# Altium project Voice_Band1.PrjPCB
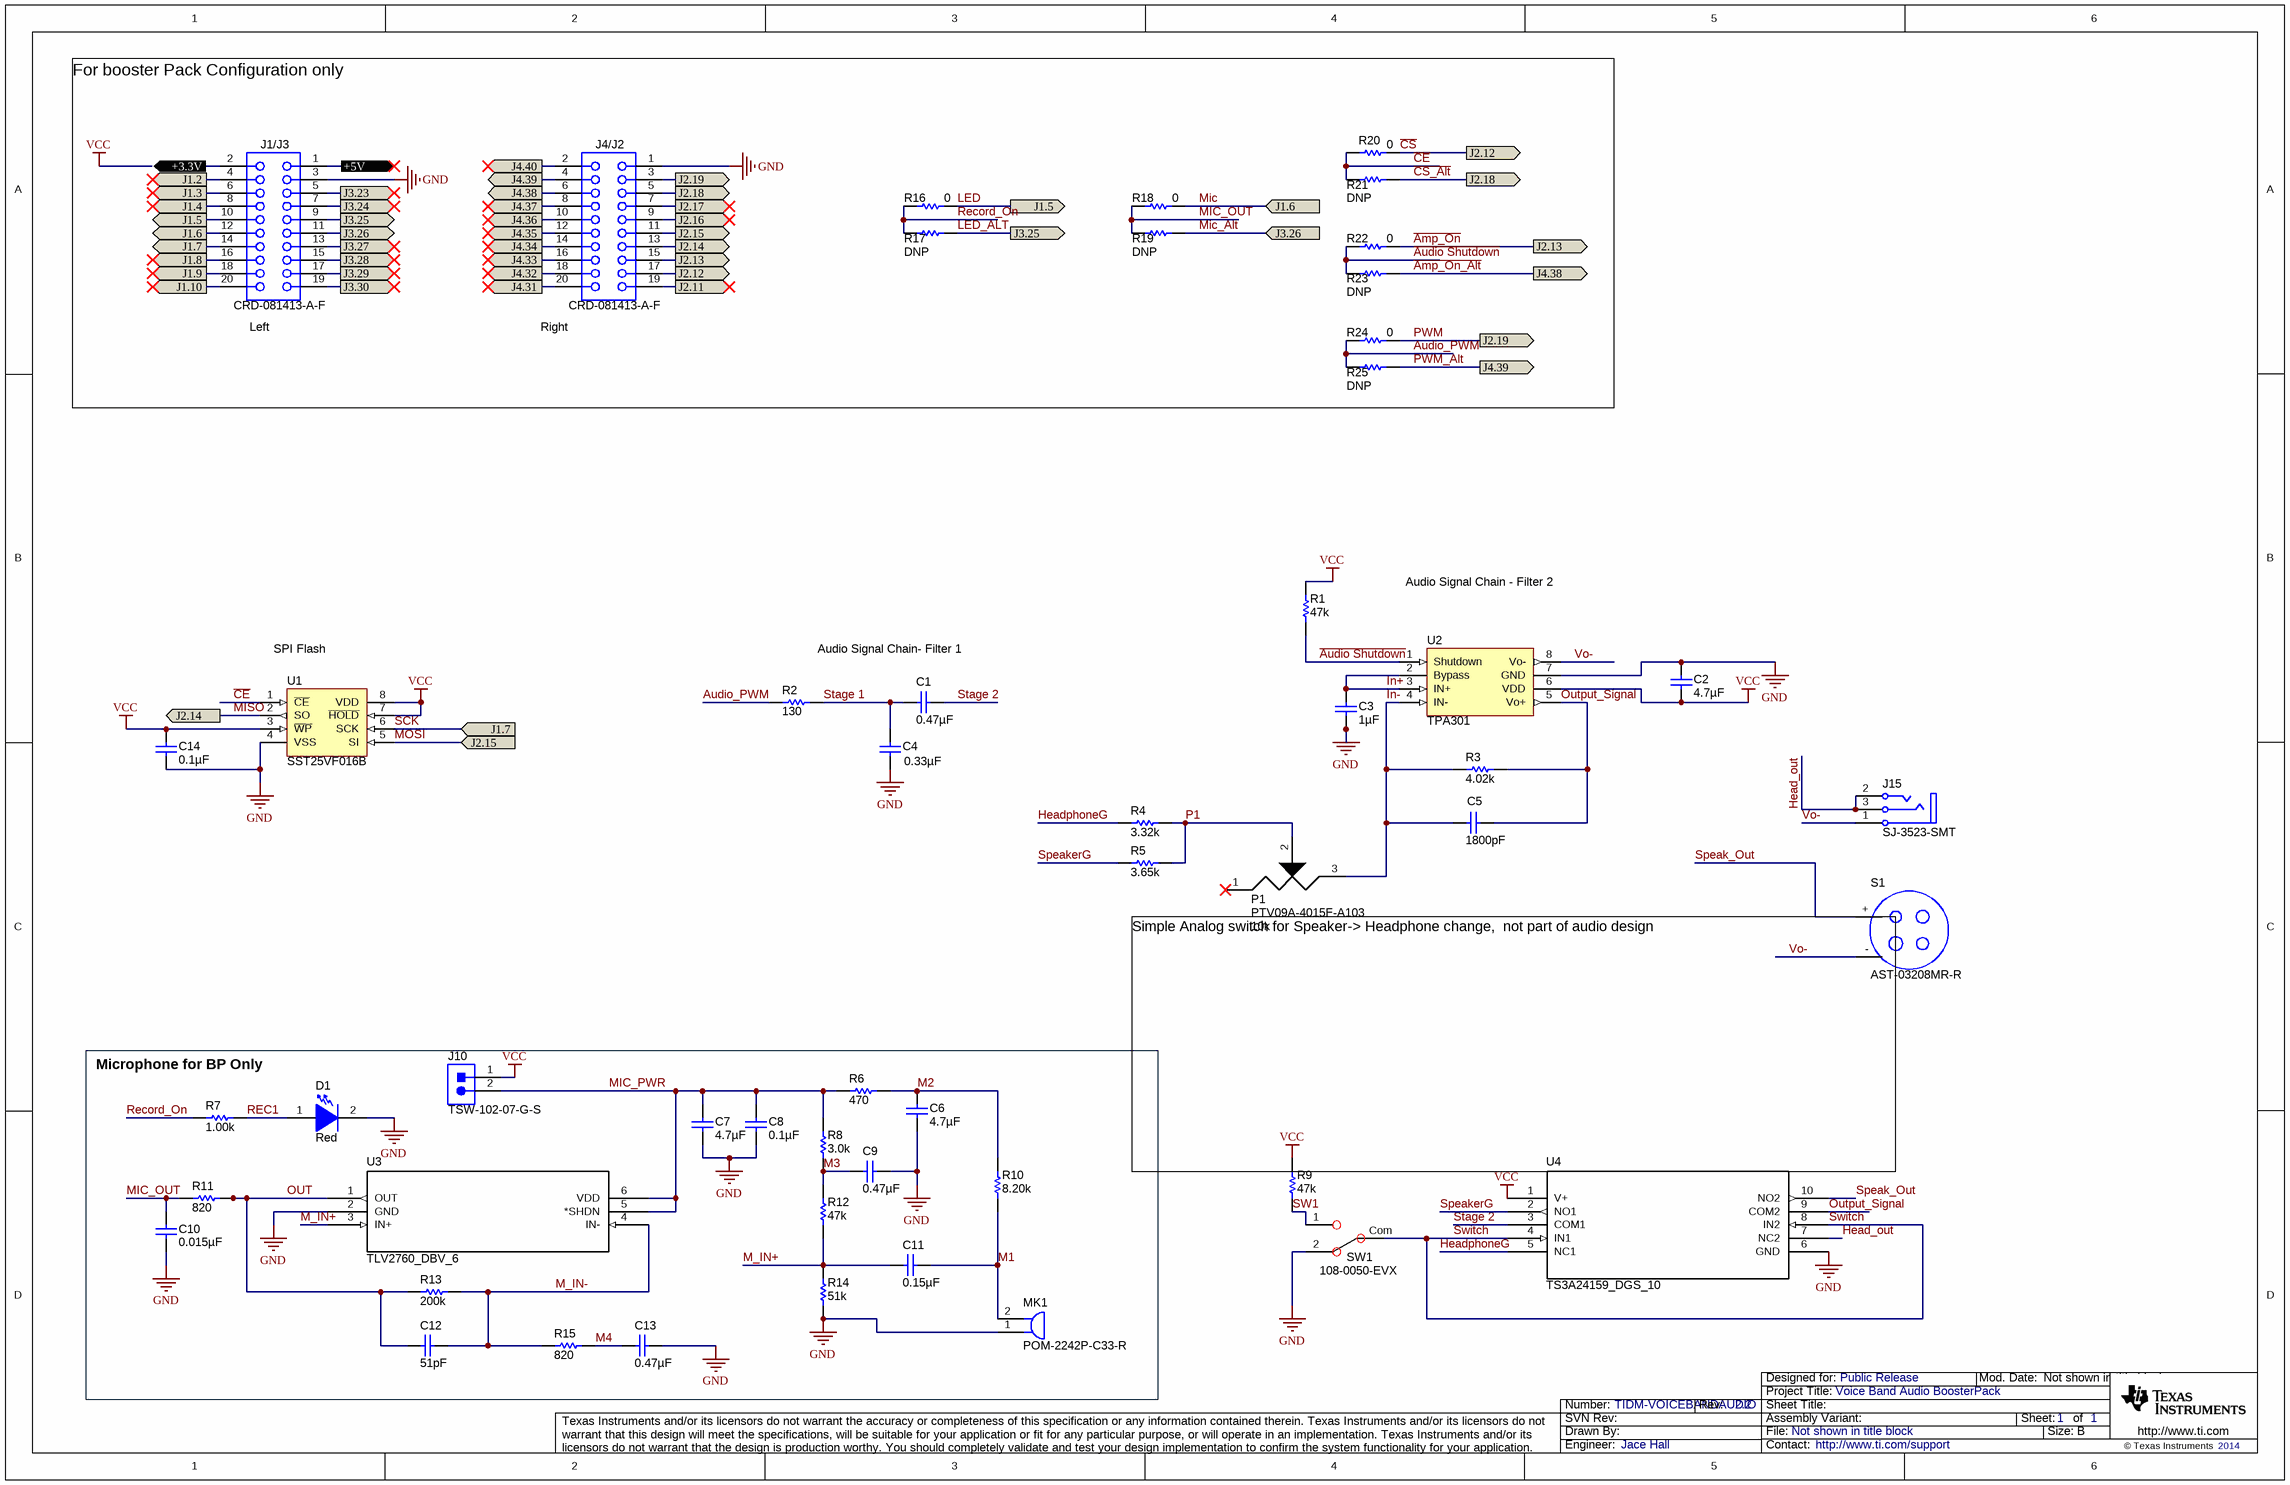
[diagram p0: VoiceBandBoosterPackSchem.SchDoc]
CopyrightYear: 2014; PCB_Layout: Jace Hall; PCB_Rev: REv 2.2; PRJ_Customer: Public Release; PRJ_Engineer: Jace Hall; PRJ_Number: TIDM-VOICEBANDAUDIO; PRJ_Title: Voice Band Audio BoosterPack; SCH_Rev: 2.2; TechSupport: http://www.ti.com/support
1 sheet, 52 parts. Net scope: flat (ports and power ports of the same name join across sheets).
Board files: VoiceBandBP_Rev2_2.PcbDoc, VoiceBandBP_Rev2.PcbDoc

## Sheet VoiceBandBoosterPackSchem.SchDoc
size 431 x 279 mm; Date: Not shown in title block; ApprovedBy: Not shown in title block; CheckedBy: Not shown in title block; Author: Not shown in title block; CompanyName: Not shown in title block; Engineer: Not shown in title block; Organization: Not shown in title block; Address1: Not shown in title block; Address2: Not shown in title block; Address3: Not shown in title block; Address4: Not shown in title block; DocumentNumber: 1; Revision: Use project parameter SCH_Rev; SheetNumber: 1; SheetTotal: 1; PageSetup: Record=PageOptions¦CenterHorizontal=True¦CenterVertical=True¦PrintScale=1.00¦XCorrection=1.00¦YCorrection=1.00¦PrintKind=0¦BorderSize=5000000¦LeftOffset=0¦BottomOffset=0¦Orientation=2¦PaperLength=1000¦PaperWidth=1000¦Scale=100¦PaperSource=15¦PrintQuality=600¦MediaType=1¦DitherType=10¦PaperKind=Letter¦PrintScaleMode=1

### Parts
C1  ValueDisplayed: 0.47µF  [0603]  (hidden comment: GRM188R60J474KA01D)
C2  ValueDisplayed: 4.7µF  [0603]  (hidden comment: GRM188R60J475KE19D)
C3  ValueDisplayed: 1µF  [0603]  (hidden comment: GRM185R60J105KE26D)
C4  ValueDisplayed: 0.33µF  [0603]  (hidden comment: GRM188R60J334KA01D)
C5  ValueDisplayed: 1800pF  [0603]  (hidden comment: GRM188R71E182KA01D)
C6  ValueDisplayed: 4.7µF  [0603]  (hidden comment: GRM188R60J475KE19D)
C7  ValueDisplayed: 4.7µF  [0603]  (hidden comment: GRM188R60J475KE19D)
C8  ValueDisplayed: 0.1µF  [0603]  (hidden comment: GRM188R70J104KA01D)
C9  ValueDisplayed: 0.47µF  [0603]  (hidden comment: GRM188R60J474KA01D)
C10  ValueDisplayed: 0.015µF  [0603]  (hidden comment: GRM188R71C153KA01D)
C11  ValueDisplayed: 0.15µF  [0603]  (hidden comment: GRM188R61A154KA01D)
C12  ValueDisplayed: 51pF  [0603]  (hidden comment: GRM1885C1H510JA01D)
C13  ValueDisplayed: 0.47µF  [0603]  (hidden comment: GRM188R60J474KA01D)
C14  ValueDisplayed: 0.1µF  [0603]  (hidden comment: GRM188R70J104KA01D)
D1  value Red  [LED_LTST-C170]  (hidden comment: LTST-C170KRKT)
J1/J3  CRD-081413-A-F  [CONN_SSW-110-23-F-D]
J4/J2  CRD-081413-A-F  [CONN_SSW-110-23-F-D]
J10  TSW-102-07-G-S  [TSW-102-07-G-S]
J15  SJ-3523-SMT  [CUI_SJ-3523-SMT]
MK1  POM-2242P-C33-R  [MIC_POM-2242P-C33-R]
P1  PTV09A-4015F-A103  Resistance: 10k  [Pot1_PCB]
R1  value 47k  [0603]  (hidden comment: CRCW060347K0JNEA)
R2  value 130  [0603]  (hidden comment: RG1608P-131-B-T5)
R3  value 4.02k  [0603]  (hidden comment: TNPW06034K02BEEA)
R4  value 3.32k  [0603]  (hidden comment: TNPW06033K32BEEA)
R5  value 3.65k  [0603]  (hidden comment: TNPW06033K65BEEA)
R6  value 470  [0603]  (hidden comment: RC0603FR-07470RL)
R7  value 1.00k  [0603]  (hidden comment: RC0603FR-071KL)
R8  value 3.0k  [0603]  (hidden comment: RC0603JR-073KL)
R9  value 47k  [0603]  (hidden comment: CRCW060347K0JNEA)
R10  value 8.20k  [0603]  (hidden comment: RC0603FR-078K2L)
R11  value 820  [0603]  (hidden comment: RC0603FR-07820RL)
R12  value 47k  [0603]  (hidden comment: CRCW060347K0JNEA)
R13  value 200k  [0603]  (hidden comment: RC0603FR-07200KL)
R14  value 51k  [0603]  (hidden comment: ERA-3AED513V)
R15  value 820  [0603]  (hidden comment: RC0603FR-07820RL)
R16  value 0  [0805_HV]  (hidden comment: CRCW08050000Z0EA)
R17  DNP  [0805_HV]
R18  value 0  [0805_HV]  (hidden comment: CRCW08050000Z0EA)
R19  DNP  [0805_HV]
R20  Res_ohm: 0  [0805_HV]  (hidden comment: CRCW08050000Z0EA)
R21  DNP  [0805_HV]
R22  value 0  [0805_HV]  (hidden comment: CRCW08050000Z0EA)
R23  DNP  [0805_HV]
R24  value 0  [0805_HV]  (hidden comment: CRCW08050000Z0EA)
R25  DNP  [0805_HV]
S1  AST-03208MR-R  [Speaker]
SW1  Supplier Part Number 1: 108-0050-EVX  [Switch__Toggle]  (hidden comment: Used in BOM report)
U1  SST25VF016B  [8-SOIC 5.4mm x 5.4mm]
U2  TPA301  [8-SOP 1.27mm pitch]
U3  TLV2760_DBV_6  [SOT95P280X145-6N]
U4  TS3A24159_DGS_10  [DGS10]

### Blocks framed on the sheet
Microphone for BP Only: C6-C13 D1 J10 MK1 R6-R8 R10-R15 U3

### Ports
+3.3V, +5V, J1.2, J1.3, J1.4, J1.5, J1.5 (out), J1.6, J1.6 (in), J1.7, J1.8, J1.9, J1.10, J2.11, J2.12, J2.13, J2.14, J2.14 (out), J2.15, J2.15 (in), J2.16, J2.17, J2.18, J2.19, J3.23, J3.24, J3.25, J3.25 (out), J3.26, J3.26 (in), J3.27, J3.28, J3.29, J3.30, J4.31, J4.32, J4.33, J4.34, J4.35, J4.36, J4.37, J4.38, J4.39, J4.40

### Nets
GND: C2.1 C3.2 C4.2 C6.2 C7.2 C8.2 C9.1 C10.2 C13.1 C14.2 D1.2(K) J1/J3.3 J4/J2.1 MK1.1 R14.1 SW1.2 U1.4(VSS) U2.7(GND) U3.2(GND) U4.6(GND)
VCC: C2.2 C14.1 J1/J3.2 J10.1 R1.2 R9.2 U1.3(~{WP}) U1.7(~{HOLD}) U1.8(VDD) U2.6(VDD) U4.1(V+) ; port +3.3V
+5V: J1/J3.1 ; port +5V
~{Amp_On}: J4/J2.15 R22.2 ; port J2.13
~{Amp_On_Alt}: J4/J2.6 R23.2 ; port J4.38
~{CS}: J4/J2.17 R20.2 ; port J2.12
~{CS_Alt}: J4/J2.5 R21.2 ; port J2.18
~{Audio Shutdown}: R1.1 R22.1 R23.1 U2.1(Shutdown)
Audio_PWM: R2.1 R24.1 R25.1
~{CE}: R20.1 R21.1 U1.1(~{CE})
Head_out: J15.2(L) J15.3(R) U4.7(NC2)
HeadphoneG: R4.1 U4.5(NC1)
In+: C3.1 U2.2(Bypass) U2.3(IN+)
In-: C5.2 P1.3 R3.1 U2.4(IN-)
J1.2: J1/J3.4 ; port J1.2
J1.3: J1/J3.6 ; port J1.3
J1.4: J1/J3.8 ; port J1.4
J1.8: J1/J3.16 ; port J1.8
J1.9: J1/J3.18 ; port J1.9
J1.10: J1/J3.20 ; port J1.10
J2.11: J4/J2.19 ; port J2.11
J2.16: J4/J2.9 ; port J2.16
J2.17: J4/J2.7 ; port J2.17
J3.23: J1/J3.5 ; port J3.23
J3.24: J1/J3.7 ; port J3.24
J3.27: J1/J3.13 ; port J3.27
J3.28: J1/J3.15 ; port J3.28
J3.29: J1/J3.17 ; port J3.29
J3.30: J1/J3.19 ; port J3.30
J4.31: J4/J2.20 ; port J4.31
J4.32: J4/J2.18 ; port J4.32
J4.33: J4/J2.16 ; port J4.33
J4.34: J4/J2.14 ; port J4.34
J4.35: J4/J2.12 ; port J4.35
J4.36: J4/J2.10 ; port J4.36
J4.37: J4/J2.8 ; port J4.37
J4.40: J4/J2.2 ; port J4.40
LED: J1/J3.10 R16.2 ; port J1.5
LED_ALT: J1/J3.9 R17.2 ; port J3.25
M1: C11.1 MK1.2 R10.1
M2: C6.1 R6.2 R10.2
M3: C9.2 R8.1 R12.2
M4: C13.2 R15.2
M_IN+: C11.2 R12.1 R14.2 U3.3(IN+)
M_IN-: C12.1 R13.2 R15.1 U3.4(IN-)
Mic: J1/J3.12 R18.2 ; port J1.6
Mic_Alt: J1/J3.11 R19.2 ; port J3.26
MIC_OUT: C10.1 R11.1 R18.1 R19.1
MIC_PWR: C7.1 C8.1 J10.2 R6.1 R8.2 U3.5(*SHDN) U3.6(VDD)
MISO: J4/J2.13 U1.2(SO) ; port J2.14
MOSI: J4/J2.11 U1.5(SI) ; port J2.15
OUT: C12.2 R11.2 R13.1 U3.1(OUT)
Output_Signal: C5.1 R3.2 U2.5(Vo+) U4.9(COM2)
P1: P1.2 R4.2 R5.2
PWM: J4/J2.3 R24.2 ; port J2.19
PWM_Alt: J4/J2.4 R25.2 ; port J4.39
REC1: D1.1(A) R7.2
Record_On: R7.1 R16.1 R17.1
SCK: J1/J3.14 U1.6(SCK) ; port J1.7
Speak_Out: S1.+ U4.10(NO2)
SpeakerG: R5.1 U4.2(NO1)
Stage 1: C1.2 C4.1 R2.2
Stage 2: C1.1 U4.3(COM1)
SW1: R9.1 SW1.1
Switch: SW1.Com U4.4(IN1) U4.8(IN2)
Vo-: J15.1(S) S1.- U2.8(Vo-)

Not connected (* = marked no-connect by the designer): P1 1*

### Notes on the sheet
- (near J1/J3) Left
- (near J4/J2) Right
- For booster Pack Configuration only
- Audio Signal Chain - Filter 2
- (near U1) SPI Flash
- Audio Signal Chain- Filter 1
- Simple Analog switch for Speaker-> Headphone change,  not part of audio design

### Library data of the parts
C1 C9 C13 = GRM188R60J474KA01D: CAP, CERM, 0.47uF, 6.3V, +/-10%, X5R, 0603; Manufacturer: MuRata; Polarized: N; CompType: Capacitor; U/M: EA; Cap_F: 0.00000047; Tolerance_%: 10; Value1: Unknown; VDC_V: 6.3; TaMin_C: -55; TaMax_C: 85
C2 C6 C7 = GRM188R60J475KE19D: CAP, CERM, 4.7uF, 6.3V, +/-10%, X5R, 0603; Manufacturer: MuRata; Polarized: N; CompType: Capacitor; U/M: EA; Cap_F: 0.0000047; Tolerance_%: 10; ESR_Ohm: 0.005; Value1: 0.005 ohm; VDC_V: 6.3; IRMS_A: 2; TaMin_C: -55; TaMax_C: 85
C3 = GRM185R60J105KE26D: CAP, CERM, 1uF, 6.3V, +/-10%, X5R, 0603; Manufacturer: MuRata; Polarized: N; CompType: Capacitor; U/M: EA; Cap_F: 0.000001; Tolerance_%: 10; Value1: Unknown; VDC_V: 6.3; TaMin_C: -55; TaMax_C: 85
C4 = GRM188R60J334KA01D: CAP, CERM, 0.33uF, 6.3V, +/-10%, X5R, 0603; Manufacturer: MuRata; Polarized: N; CompType: Capacitor; U/M: EA; Cap_F: 0.00000033; Tolerance_%: 10; Value1: Unknown; VDC_V: 6.3; TaMin_C: -55; TaMax_C: 85
C5 = GRM188R71E182KA01D: CAP, CERM, 1800pF, 25V, +/-10%, X7R, 0603; Manufacturer: MuRata; Polarized: N; CompType: Capacitor; U/M: EA; Cap_F: 0.0000000018; Tolerance_%: 10; Value1: Unknown; VDC_V: 25; TaMin_C: -55; TaMax_C: 125
C8 C14 = GRM188R70J104KA01D: CAP, CERM, 0.1uF, 6.3V, +/-10%, X7R, 0603; Manufacturer: MuRata; Polarized: N; CompType: Capacitor; U/M: EA; Cap_F: 0.0000001; Tolerance_%: 10; Value1: Unknown; VDC_V: 6.3; TaMin_C: -55; TaMax_C: 125
C10 = GRM188R71C153KA01D: CAP, CERM, 0.015uF, 16V, +/-10%, X7R, 0603; Manufacturer: MuRata; Polarized: N; CompType: Capacitor; U/M: EA; Cap_F: 0.000000015; Tolerance_%: 10; Value1: Unknown; VDC_V: 16; TaMin_C: -55; TaMax_C: 125
C11 = GRM188R61A154KA01D: CAP, CERM, 0.15uF, 10V, +/-10%, X5R, 0603; Manufacturer: MuRata; Polarized: N; CompType: Capacitor; U/M: EA; Cap_F: 0.00000015; Tolerance_%: 10; Value1: Unknown; TaMin_C: -55; TaMax_C: 85
C12 = GRM1885C1H510JA01D: CAP, CERM, 51pF, 50V, +/-5%, C0G/NP0, 0603; Manufacturer: MuRata; Polarized: N; CompType: Capacitor; U/M: EA; Cap_F: 0.000000000051; Tolerance_%: 5; Value1: Unknown; VDC_V: 50; TaMin_C: -55; TaMax_C: 125
D1 = LTST-C170KRKT: LED, Red, SMD; Manufacturer: Lite-On; Type: AlInGaP; Vf_V: 2; Value2: 2V; Io_A: 20; Value1: W; U/M: EA
J1/J3 J4/J2 = SSW-110-23-F-D: Connector, Receptacle, 100mil, 10x2, Gold plated, TH; Manufacturer: Major League Electronics; Alternate Manufacturer: Samtec, Inc.; SymbolCreator: a0412235; U/M: EA
J10 = TSW-102-07-G-S: Header, TH, 100mil, 2x1, Gold plated, 230 mil above insulator; Manufacturer: Samtec; SymbolCreator: a0412235; U/M: EA
J15 = SJ-3523-SMT: Connector, Audio Jack, 3.5mm, Stereo, SMD; Manufacturer: CUI Inc.; SymbolCreator: codlsc; U/M: EA
MK1 = POM-2242P-C33-R: Microphone, Condenser, Analog, Omnidirectional, -42DB, TH; Manufacturer: PUI Audio; SymbolCreator: a0412235
P1 = Pot: Potentiometer; Manufacturer: Bourns; SymbolCreator: Use a-id; U/M: EA, IN, or GM; Tolerance: 20%
R1 R9 R12 = CRCW060347K0JNEA: RES, 47k ohm, 5%, 0.1W, 0603; Manufacturer: Vishay-Dale; CompType: Resistor; Res_ohm: 47000; Value_Code: 47k0; Tolerance_%: 5; Power_W: 0.1; VDC_V: 75; TempCo: 200 ppm/C; EIA_Code: E24; U/M: EA
R2 = RG1608P-131-B-T5: RES, 130 ohm, 0.1%, 0.1W, 0603; Manufacturer: Susumu Co Ltd; CompType: Resistor; Value_Code: 130R; Tolerance_%: 0.1; VDC_V: 75; TempCo: 25 ppm/C; EIA_Code: E192; U/M: EA
R3 = RT0603BRD074K02L: RES, 4.02k ohm, 0.1%, 100mW, 0603; Manufacturer: Vishay; CompType: Resistor; Res_ohm: 4020; Value_Code: 4k02; Tolerance_%: 0.1; VDC_V: 75; TempCo: 25 ppm/C; EIA_Code: E192; U/M: EA
R4 = RT0603BRD073K32L: RES, 3.32k ohm, 0.1%, 100mW, 0603; Manufacturer: Vishay; CompType: Resistor; Res_ohm: 3320; Value_Code: 3k32; Tolerance_%: 0.1; VDC_V: 75; TempCo: 25 ppm/C; EIA_Code: E192; U/M: EA
R5 = RT0603BRD073K65L: RES, 3.65k ohm, 0.1%, 100mW, 0603; Manufacturer: Vishay; CompType: Resistor; Res_ohm: 3650; Value_Code: 3k65; Tolerance_%: 0.1; VDC_V: 75; TempCo: 25 ppm/C; EIA_Code: E192; U/M: EA
R6 = RC0603FR-07470RL: RES, 470 ohm, 1%, 0.1W, 0603; Manufacturer: Yageo America; CompType: Resistor; Value_Code: 470R; Tolerance_%: 1; Power_W: 0.1; VDC_V: 150; TempCo: 200 ppm/C; U/M: EA
R7 = RC0603FR-071KL: RES, 1.00k ohm, 1%, 0.1W, 0603; Manufacturer: Yageo America; CompType: Resistor; Res_ohm: 1000; Value_Code: 1k00; Tolerance_%: 1; Power_W: 0.1; VDC_V: 150; TempCo: 200 ppm/C; EIA_Code: E96; U/M: EA
R8 = RC0603JR-073KL: RES, 3.0k ohm, 5%, 0.1W, 0603; Manufacturer: Yageo America; CompType: Resistor; Res_ohm: 3000; Value_Code: 3k00; Tolerance_%: 5; Power_W: 0.1; VDC_V: 50; TempCo: 100 ppm/C; EIA_Code: E24; U/M: EA
R10 = RC0603FR-078K2L: RES, 8.20k ohm, 1%, 0.1W, 0603; Manufacturer: Yageo America; CompType: Resistor; Res_ohm: 8200; Value_Code: 8k20; Tolerance_%: 1; Power_W: 0.1; VDC_V: 150; TempCo: 200 ppm/C; U/M: EA
R11 R15 = RC0603FR-07820RL: RES, 820 ohm, 1%, 0.1W, 0603; Manufacturer: Yageo America; CompType: Resistor; Value_Code: 820R; Tolerance_%: 1; Power_W: 0.1; VDC_V: 150; TempCo: 200 ppm/C; U/M: EA
R13 = RC0603FR-07200KL: RES, 200k ohm, 1%, 0.1W, 0603; Manufacturer: Yageo America; CompType: Resistor; Res_ohm: 200000; Tolerance_%: 1; Power_W: 0.1; VDC_V: 150; TempCo: 200 ppm/C; EIA_Code: E96; U/M: EA
R14 = RT0603DRE0750K5L: RES, 51kohm, 0.5%, 100mW, 0603; Manufacturer: Panasonic; CompType: Resistor; Res_ohm: 51000; Tolerance_%: 0.5; VDC_V: 75; TempCo: 50 ppm/C; EIA_Code: E192; U/M: EA
R16 R18 R20 R22 R24 = CRCW08050000Z0EA: RES, 0 ohm, 5%, 0.125W, 0805; Manufacturer: Vishay-Dale; CompType: Resistor; Value_Code: 0000; Tolerance_%: 5; Power_W: 0.125; VDC_V: 150; TempCo: 200 ppm/C; EIA_Code: E24; U/M: EA
R17 R19 R21 R23 = CRCW08050000Z0EA: RES, 0 ohm, 5%, 0.125W, 0805; Manufacturer: Vishay-Dale; CompType: Resistor; Res_ohm: 0; Value_Code: 0000; Tolerance_%: 5; Power_W: 0.125; VDC_V: 150; TempCo: 200 ppm/C; EIA_Code: E24; U/M: EA
R25 = CRCW08050000Z0EA: RES, 0 ohm, 5%, 0.125W, 0805; Manufacturer: Vishay-Dale; CompType: Resistor; Value: 0; Value_Code: 0000; Tolerance_%: 5; Power_W: 0.125; VDC_V: 150; TempCo: 200 ppm/C; EIA_Code: E24; U/M: EA
S1 = Speaker: Manufacturer: PUI Audio; SymbolVersion: use current date i.e. 2008-05-20; SymbolCreator: Use a-id; Impedance: 8 ohm; Frequency Range: 500-200000Hz; Max Input: 0.2W; CompType: Used in some BOM reports.  Useful for finding later.; U/M: EA, IN, or GM
SW1 = Switch -- Toggle: SymbolVersion: use current date i.e. 2008-05-20; SymbolCreator: Use a-id; CompType: Used in some BOM reports.  Useful for finding later.; U/M: EA, IN, or GM
U1 = SST25VF016B: 16Mbit SPI Flash; Manufacturer: SST; SymbolCreator: a0272566; U/M: EA, IN, or GM
U2 = TPA301: 350mW Mono Audio Power Amplifer; Manufacturer: Texas Instruments; SymbolCreator: a0272566; CompType: Mono Audio Amplifier; U/M: EA, IN, or GM
U3 = TLV2760_DBV_6: Imported; Vendor: Texas Instruments; PACKAGE_DESIGNATOR: DBV; PIN_COUNT: 6; FAMILY_NAME: LOW POWER; INDUSTRY_STD_PKG_TYPE: SOT-23
U4 = TS3A24159_DGS_10: Imported; Vendor: Texas Instruments; PACKAGE_DESIGNATOR: DGS; PIN_COUNT: 10; FAMILY_NAME: ANALOG SWITCH OR MULTIPLEXER (less than or equal to 5V); INDUSTRY_STD_PKG_TYPE: MSOP

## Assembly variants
001: not fitted FID1 FID2 FID3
